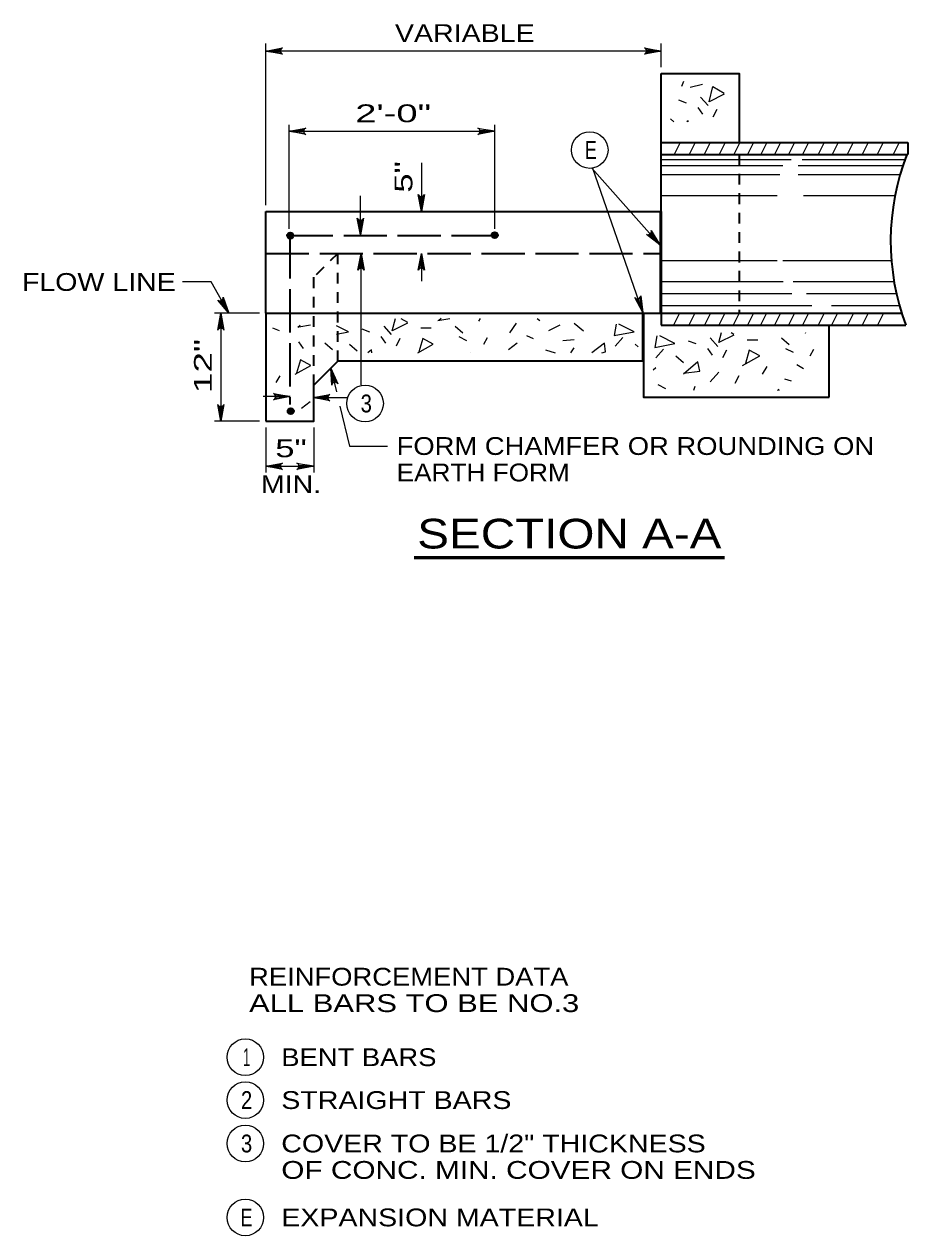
# Model space of a CAD drawing. Extents: x 2 to 114, y -129 to 32.
# Drawn here: x 65.3 to 114.4, y -35.3 to 32 of the extents above; entities that cross this region are included whole.
import ezdxf
from ezdxf.enums import TextEntityAlignment as Align

# ---------------------------------------------------------------- set-up
doc = ezdxf.new("R2010")
doc.units = 0
doc.header["$LTSCALE"] = 0.4
doc.linetypes.add('LONG_DASHED', pattern=[7.5, 6, -1.5])
doc.linetypes.add('SHORT_DASHED', pattern=[2.7, 1.5, -1.2])
for name, color, linetype, lineweight in [('1', 7, 'Continuous', 35), ('10', 7, 'Continuous', 13), ('12', 7, 'Continuous', 53), ('13', 7, 'Continuous', 25), ('6', 7, 'Continuous', 13)]:
    doc.layers.add(name, color=color, linetype=linetype, lineweight=lineweight)

msp = doc.modelspace()

# ---------------------------------------------------------------- linework, layer by layer
at = {"layer": '1'}
for p, q in [((100.7378, 21.6074), (100.7378, 29.2741)), ((100.7378, 25.4408), (114.4448, 25.4408)), ((114.4448, 25.4408), (114.4448, 24.7741)), ((100.7378, 24.7741), (114.4448, 24.7741)), ((78.7378, 21.6074), (100.7378, 21.6074)), ((78.7378, 15.9408), (78.7378, 21.6074)), ((100.7378, 21.6074), (100.7378, 15.2741)), ((78.7378, 15.9408), (100.7378, 15.9408)), ((78.7378, 15.9408), (78.7378, 9.9408)), ((100.7378, 15.9408), (114.1068, 15.9408)), ((100.7378, 15.2741), (114.3351, 15.2741)), ((110.0711, 11.2741), (110.0711, 15.2741))]:
    msp.add_line(p, q, dxfattribs=at)
at = {"layer": '1', "linetype": 'SHORT_DASHED'}
for p, q in [((105.0711, 24.7741), (105.0711, 15.9408)), ((82.7378, 19.2741), (81.4045, 17.9408)), ((82.7378, 13.2741), (82.7378, 19.2741)), ((81.4045, 11.9408), (81.4045, 17.9408))]:
    msp.add_line(p, q, dxfattribs=at)
at = {"layer": '1', "linetype": 'LONG_DASHED'}
for p, q in [((80.0711, 20.2741), (80.0711, 10.8778)), ((80.0711, 20.2741), (91.329, 20.2741)), ((78.7378, 19.2741), (100.7378, 19.2741))]:
    msp.add_line(p, q, dxfattribs=at)
at = {"layer": '1'}
for points in [[(100.7378, 29.2741), (105.0711, 29.2741), (105.0711, 25.4408)], [(99.7378, 15.9408), (99.7378, 11.2741), (110.0711, 11.2741)], [(99.7378, 13.2741), (82.7378, 13.2741), (81.4045, 11.9408)], [(78.7378, 9.9408), (81.4045, 9.9408), (81.4045, 11.9408)]]:
    msp.add_lwpolyline(points, dxfattribs=at)
for centre, radius in [((80.0977, 20.2589), 0.1667), ((80.0977, 20.2589), 0.125), ((80.0977, 20.2589), 0.0833), ((80.0977, 20.2589), 0.0417), ((91.4703, 20.2878), 0.1667), ((91.4703, 20.2878), 0.125), ((91.4703, 20.2878), 0.0833), ((91.4703, 20.2878), 0.0417), ((80.1266, 10.5014), 0.1667), ((80.1266, 10.5014), 0.125), ((80.1266, 10.5014), 0.0833), ((80.1266, 10.5014), 0.0417)]:
    msp.add_circle(centre, radius, dxfattribs=at)
msp.add_arc((126.916, 19.9558), 13.4238, 158.96483, 200.41147, dxfattribs=at)
at = {"layer": '10'}
for p, q in [((78.7378, 21.9574), (78.7378, 30.9362)), ((100.7378, 30.5196), (78.7378, 30.5196)), ((100.7378, 29.6241), (100.7378, 30.9362)), ((80.0398, 20.6378), (80.0398, 26.4135)), ((91.4703, 20.6378), (91.4703, 26.4135)), ((80.0398, 26.0635), (91.4703, 26.0635)), ((87.3901, 24.298), (87.3901, 21.6074)), ((96.8661, 24.0045), (100.6617, 19.7394)), ((96.9061, 24.0097), (99.4847, 16.5975)), ((84.0043, 20.3023), (84.0043, 22.4776)), ((84.035, 11.9581), (84.035, 19.2741)), ((87.3901, 19.2741), (87.3901, 17.7359)), ((78.3878, 15.9408), (75.8878, 15.9408)), ((76.2378, 15.9408), (76.2378, 9.9408)), ((82.3581, 12.8943), (82.6757, 11.5743)), ((80.0977, 11.3121), (78.5977, 11.3121)), ((81.371, 11.2542), (83.2519, 11.2542)), ((82.8651, 10.7872), (83.4001, 8.5636)), ((78.3878, 9.9408), (75.8878, 9.9408)), ((78.7378, 9.5908), (78.7378, 7.0908)), ((81.4045, 9.5908), (81.4045, 7.0908)), ((83.4001, 8.5636), (85.5161, 8.5636)), ((78.7378, 7.4408), (81.4045, 7.4408))]:
    msp.add_line(p, q, dxfattribs=at)
for points in [[(78.7378, 30.5196), (79.6699, 30.6943), (79.5981, 30.6446), (79.561, 30.5821), (79.5503, 30.5196), (79.561, 30.4571), (79.5981, 30.3946), (79.6699, 30.3448), (78.7378, 30.5196), (79.5981, 30.3946), (79.561, 30.4571), (78.7378, 30.5196), (79.5503, 30.5196), (79.561, 30.5821), (78.7378, 30.5196), (79.5981, 30.6446)], [(100.7378, 30.5196), (99.8057, 30.3448), (99.8776, 30.3946), (99.9146, 30.4571), (99.9253, 30.5196), (99.9146, 30.5821), (99.8776, 30.6446), (99.8057, 30.6943), (100.7378, 30.5196), (99.8776, 30.6446), (99.9146, 30.5821), (100.7378, 30.5196), (99.9253, 30.5196), (99.9146, 30.4571), (100.7378, 30.5196), (99.8776, 30.3946)], [(80.0398, 26.0635), (80.9719, 26.2383), (80.9001, 26.1885), (80.8631, 26.126), (80.8523, 26.0635), (80.8631, 26.001), (80.9001, 25.9385), (80.9719, 25.8887), (80.0398, 26.0635), (80.9001, 25.9385), (80.8631, 26.001), (80.0398, 26.0635), (80.8523, 26.0635), (80.8631, 26.126), (80.0398, 26.0635), (80.9001, 26.1885)], [(91.4703, 26.0635), (90.5383, 25.8887), (90.6101, 25.9385), (90.6471, 26.001), (90.6578, 26.0635), (90.6471, 26.126), (90.6101, 26.1885), (90.5383, 26.2383), (91.4703, 26.0635), (90.6101, 26.1885), (90.6471, 26.126), (91.4703, 26.0635), (90.6578, 26.0635), (90.6471, 26.001), (91.4703, 26.0635), (90.6101, 25.9385)], [(87.3901, 21.6074), (87.2153, 22.5395), (87.2651, 22.4677), (87.3276, 22.4306), (87.3901, 22.4199), (87.4526, 22.4306), (87.5151, 22.4677), (87.5648, 22.5395), (87.3901, 21.6074), (87.5151, 22.4677), (87.4526, 22.4306), (87.3901, 21.6074), (87.3901, 22.4199), (87.3276, 22.4306), (87.3901, 21.6074), (87.2651, 22.4677)], [(84.0043, 20.3023), (83.8296, 21.2344), (83.8793, 21.1626), (83.9418, 21.1255), (84.0043, 21.1148), (84.0668, 21.1255), (84.1293, 21.1626), (84.1791, 21.2344), (84.0043, 20.3023), (84.1293, 21.1626), (84.0668, 21.1255), (84.0043, 20.3023), (84.0043, 21.1148), (83.9418, 21.1255), (84.0043, 20.3023), (83.8793, 21.1626)], [(100.6617, 19.7394), (99.9115, 20.3195), (99.9964, 20.2989), (100.0677, 20.3128), (100.1215, 20.3463), (100.1611, 20.3959), (100.1832, 20.4651), (100.1726, 20.5518), (100.6617, 19.7394), (100.1832, 20.4651), (100.1611, 20.3959), (100.6617, 19.7394), (100.1215, 20.3463), (100.0677, 20.3128), (100.6617, 19.7394), (99.9964, 20.2989)], [(84.035, 19.2741), (84.2098, 18.342), (84.16, 18.4138), (84.0975, 18.4509), (84.035, 18.4616), (83.9725, 18.4509), (83.91, 18.4138), (83.8603, 18.342), (84.035, 19.2741), (83.91, 18.4138), (83.9725, 18.4509), (84.035, 19.2741), (84.035, 18.4616), (84.0975, 18.4509), (84.035, 19.2741), (84.16, 18.4138)], [(87.3901, 19.2741), (87.5648, 18.342), (87.5151, 18.4138), (87.4526, 18.4509), (87.3901, 18.4616), (87.3276, 18.4509), (87.2651, 18.4138), (87.2153, 18.342), (87.3901, 19.2741), (87.2651, 18.4138), (87.3276, 18.4509), (87.3901, 19.2741), (87.3901, 18.4616), (87.4526, 18.4509), (87.3901, 19.2741), (87.5151, 18.4138)], [(76.6821, 15.9408), (75.6991, 17.682), (74.1076, 17.682)], [(76.6821, 15.9408), (76.0717, 16.6665), (76.1503, 16.6284), (76.223, 16.6269), (76.2827, 16.6483), (76.3318, 16.6884), (76.368, 16.7513), (76.3761, 16.8383), (76.6821, 15.9408), (76.368, 16.7513), (76.3318, 16.6884), (76.6821, 15.9408), (76.2827, 16.6483), (76.223, 16.6269), (76.6821, 15.9408), (76.1503, 16.6284)], [(99.7049, 15.9776), (99.2559, 16.8128), (99.3251, 16.7595), (99.3959, 16.7431), (99.4587, 16.7518), (99.515, 16.781), (99.5633, 16.8352), (99.589, 16.9187), (99.7049, 15.9776), (99.5633, 16.8352), (99.515, 16.781), (99.7049, 15.9776), (99.4587, 16.7518), (99.3959, 16.7431), (99.7049, 15.9776), (99.3251, 16.7595)], [(76.2378, 15.9408), (76.4126, 15.0087), (76.3628, 15.0805), (76.3003, 15.1175), (76.2378, 15.1283), (76.1753, 15.1175), (76.1128, 15.0805), (76.0631, 15.0087), (76.2378, 15.9408), (76.1128, 15.0805), (76.1753, 15.1175), (76.2378, 15.9408), (76.2378, 15.1283), (76.3003, 15.1175), (76.2378, 15.9408), (76.3628, 15.0805)], [(82.3581, 12.8943), (82.746, 12.029), (82.6808, 12.0872), (82.6114, 12.1086), (82.5481, 12.1044), (82.4899, 12.0793), (82.4378, 12.0287), (82.4062, 11.9473), (82.3581, 12.8943), (82.4378, 12.0287), (82.4899, 12.0793), (82.3581, 12.8943), (82.5481, 12.1044), (82.6114, 12.1086), (82.3581, 12.8943), (82.6808, 12.0872)], [(80.0977, 11.3121), (79.1656, 11.1373), (79.2375, 11.1871), (79.2745, 11.2496), (79.2852, 11.3121), (79.2745, 11.3746), (79.2375, 11.4371), (79.1656, 11.4869), (80.0977, 11.3121), (79.2375, 11.4371), (79.2745, 11.3746), (80.0977, 11.3121), (79.2852, 11.3121), (79.2745, 11.2496), (80.0977, 11.3121), (79.2375, 11.1871)], [(76.2378, 9.9408), (76.0631, 10.8728), (76.1128, 10.801), (76.1753, 10.764), (76.2378, 10.7533), (76.3003, 10.764), (76.3628, 10.801), (76.4126, 10.8728), (76.2378, 9.9408), (76.3628, 10.801), (76.3003, 10.764), (76.2378, 9.9408), (76.2378, 10.7533), (76.1753, 10.764), (76.2378, 9.9408), (76.1128, 10.801)], [(81.371, 11.2542), (82.3031, 11.429), (82.2312, 11.3792), (82.1942, 11.3167), (82.1835, 11.2542), (82.1942, 11.1917), (82.2312, 11.1292), (82.3031, 11.0794), (81.371, 11.2542), (82.2312, 11.1292), (82.1942, 11.1917), (81.371, 11.2542), (82.1835, 11.2542), (82.1942, 11.3167), (81.371, 11.2542), (82.2312, 11.3792)], [(78.7378, 7.4408), (79.6699, 7.6155), (79.5981, 7.5658), (79.561, 7.5033), (79.5503, 7.4408), (79.561, 7.3783), (79.5981, 7.3158), (79.6699, 7.266), (78.7378, 7.4408), (79.5981, 7.3158), (79.561, 7.3783), (78.7378, 7.4408), (79.5503, 7.4408), (79.561, 7.5033), (78.7378, 7.4408), (79.5981, 7.5658)], [(81.4045, 7.4408), (80.4724, 7.266), (80.5442, 7.3158), (80.5813, 7.3783), (80.592, 7.4408), (80.5813, 7.5033), (80.5442, 7.5658), (80.4724, 7.6155), (81.4045, 7.4408), (80.5442, 7.5658), (80.5813, 7.5033), (81.4045, 7.4408), (80.592, 7.4408), (80.5813, 7.3783), (81.4045, 7.4408), (80.5442, 7.3158)]]:
    msp.add_lwpolyline(points, dxfattribs=at)
for centre in [(96.7535, 25.0174), (84.2586, 10.9296)]:
    msp.add_circle(centre, 1.0192, dxfattribs=at)
at = {"layer": '12'}
msp.add_line((86.9845, 2.3679), (104.2598, 2.3679), dxfattribs=at)
at = {"layer": '13'}
for centre in [(77.6014, -25.4092), (77.6014, -27.7921), (77.6014, -30.2049), (77.6014, -34.3154)]:
    msp.add_circle(centre, 1.0192, dxfattribs=at)
at = {"layer": '6'}
for p, q in [((101.9736, 28.8309), (101.859, 28.5444)), ((103.024, 28.6503), (102.3356, 28.4914)), ((101.7002, 27.8031), (102.1238, 27.6442)), ((102.9181, 27.9619), (103.3417, 27.4853)), ((102.7592, 27.3794), (103.024, 27.0088)), ((103.8182, 27.2735), (103.6064, 26.8499)), ((101.2499, 26.7475), (101.4354, 26.5852)), ((101.7778, 25.4408), (101.4444, 24.7741)), ((102.6201, 25.4408), (102.2867, 24.7741)), ((103.4497, 25.4408), (103.1164, 24.7741)), ((104.2795, 25.4408), (103.9461, 24.7741)), ((105.0966, 25.4408), (104.7632, 24.7741)), ((105.8634, 25.4408), (105.5301, 24.7741)), ((106.6051, 25.4408), (106.2718, 24.7741)), ((107.372, 25.4408), (107.0386, 24.7741)), ((108.1388, 25.4408), (107.8055, 24.7741)), ((108.9308, 25.4408), (108.5974, 24.7741)), ((109.7982, 25.4408), (109.4649, 24.7741)), ((110.5651, 25.4408), (110.2317, 24.7741)), ((111.4073, 25.4408), (111.074, 24.7741)), ((112.237, 25.4408), (111.9037, 24.7741)), ((113.0793, 25.4408), (112.7459, 24.7741)), ((113.9593, 25.4408), (113.6259, 24.7741)), ((100.7378, 24.4947), (107.9502, 24.4947)), ((108.5787, 24.4947), (114.2829, 24.4947)), ((100.7378, 24.1614), (107.4915, 24.1614)), ((100.7378, 23.6614), (107.3206, 23.6614)), ((108.3459, 24.1614), (114.1681, 24.1614)), ((108.3524, 23.6614), (114.0139, 23.6614)), ((100.7378, 22.4947), (107.1742, 22.4947)), ((108.6541, 22.4947), (113.7346, 22.4947)), ((100.6617, 21.6074), (100.6617, 15.9408)), ((100.7378, 18.8761), (107.1742, 18.8761)), ((107.4915, 18.8761), (113.5357, 18.8761)), ((100.7378, 17.7094), (107.5159, 17.7094)), ((108.0774, 17.7094), (113.6815, 17.7094)), ((100.7378, 17.0428), (108.0041, 17.0428)), ((108.8097, 17.0428), (113.8121, 17.0428)), ((100.7378, 16.3761), (109.1026, 16.3761)), ((110.2011, 16.3761), (113.9784, 16.3761)), ((86.2528, 15.6589), (86.6212, 15.444)), ((88.3157, 15.5499), (88.9697, 15.6589)), ((88.4958, 15.6589), (88.3686, 15.5499)), ((90.5926, 15.497), (90.6736, 15.6589)), ((93.8289, 15.6589), (93.9815, 15.5499)), ((99.6676, 15.9408), (99.6676, 13.2741)), ((101.7572, 15.9408), (101.4238, 15.2741)), ((102.5994, 15.9408), (102.2661, 15.2741)), ((103.4794, 15.9408), (103.1461, 15.2741)), ((104.2714, 15.9408), (103.938, 15.2741)), ((105.0634, 15.9408), (104.73, 15.2741)), ((105.8554, 15.9408), (105.522, 15.2741)), ((106.5845, 15.9408), (106.2511, 15.2741)), ((107.3639, 15.9408), (107.0306, 15.2741)), ((108.1433, 15.9408), (107.81, 15.2741)), ((108.9227, 15.9408), (108.5894, 15.2741)), ((109.8027, 15.9408), (109.4694, 15.2741)), ((110.5444, 15.9408), (110.2111, 15.2741)), ((111.4244, 15.9408), (111.0911, 15.2741)), ((112.2415, 15.9408), (111.9082, 15.2741)), ((113.0964, 15.9408), (112.763, 15.2741)), ((79.1075, 15.1396), (79.4782, 14.9808)), ((80.6554, 15.2617), (80.5282, 15.1527)), ((80.5745, 15.1924), (81.2285, 15.3014)), ((84.0796, 15.0734), (84.5032, 14.9145)), ((85.2974, 15.2322), (85.7211, 14.7557)), ((87.3625, 15.1263), (87.945, 15.1263)), ((89.2688, 15.2322), (89.6924, 14.8616)), ((92.6577, 15.3911), (92.287, 14.8616)), ((95.0934, 15.2852), (94.458, 14.9675)), ((95.8877, 15.3911), (96.4172, 14.9675)), ((104.6159, 14.882), (104.7794, 14.7866)), ((108.7508, 14.8396), (108.772, 14.882)), ((80.5534, 14.3519), (80.8182, 13.9812)), ((82.0216, 14.3056), (82.4452, 13.9349)), ((83.3912, 14.2261), (83.8148, 13.8555)), ((85.1386, 14.6498), (85.4034, 14.2791)), ((86.1976, 14.5438), (85.9858, 14.1202)), ((89.4806, 14.6498), (89.9042, 14.4379)), ((90.8573, 14.2261), (91.0691, 14.5968)), ((92.7106, 14.2791), (92.2341, 13.9084)), ((93.2401, 14.7027), (93.6108, 14.5438)), ((95.2523, 14.4379), (95.8877, 14.4909)), ((98.1646, 14.1202), (98.5882, 14.5968)), ((99.2766, 14.2261), (99.4524, 14.0723)), ((102.2378, 14.416), (102.6614, 14.2571)), ((103.4556, 14.5748), (103.8793, 14.0983)), ((105.5207, 14.4689), (106.1032, 14.4689)), ((107.427, 14.5748), (107.8506, 14.2042)), ((90.116, 13.7496), (90.1215, 13.7465)), ((94.2992, 13.9084), (94.8287, 13.7496)), ((95.7091, 13.7465), (95.8877, 14.0143)), ((100.4374, 13.4628), (100.861, 13.9394)), ((101.5494, 13.5687), (101.973, 13.1981)), ((103.2968, 13.9924), (103.5616, 13.6217)), ((104.3558, 13.8864), (104.144, 13.4628)), ((107.6388, 13.9924), (108.0624, 13.7806)), ((109.0155, 13.5687), (109.2274, 13.9394)), ((100.2886, 12.8058), (100.4374, 12.9333)), ((106.368, 12.5627), (106.6327, 12.9863)), ((108.2742, 13.0922), (108.6449, 12.8804)), ((79.325, 12.1011), (79.5368, 12.4718)), ((103.9322, 12.6686), (103.4556, 12.1391)), ((105.0442, 12.4568), (104.8324, 12.0332)), ((107.5859, 12.2979), (107.9565, 12.192)), ((100.5433, 11.9802), (100.9669, 11.7684)), ((102.6084, 11.8743), (102.5206, 11.6547)), ((81.1981, 11.022), (80.7216, 10.6514))]:
    msp.add_line(p, q, dxfattribs=at)
for points in [[(104.2418, 28.1208), (103.3946, 27.6972), (103.6064, 28.5444), (104.2418, 28.1737)], [(102.2402, 26.5858), (102.2297, 26.6381), (102.165, 26.582)], [(86.6212, 15.3911), (85.774, 14.9675), (85.9469, 15.6589)], [(82.668, 14.7868), (83.3382, 14.9145), (82.668, 15.2496)], [(98.2176, 15.3381), (98.1117, 14.7027), (99.2236, 14.9145), (98.3764, 15.3381)], [(104.7794, 14.7337), (103.9322, 14.3101), (104.0752, 14.882)], [(87.1875, 13.7465), (88.0509, 14.2261), (87.4684, 14.5438), (87.2566, 13.8025)], [(97.4221, 13.7465), (97.6351, 13.8025), (97.5822, 14.2791), (96.872, 13.7465)], [(100.4904, 14.6807), (100.3845, 14.0453), (101.4964, 14.2571), (100.6492, 14.6807)], [(84.6415, 13.7465), (84.6091, 13.9084), (84.4222, 13.7465)], [(105.256, 13.0392), (106.2091, 13.5687), (105.6266, 13.8864), (105.4148, 13.1451)], [(80.3792, 12.5549), (81.2426, 13.0345), (80.6602, 13.3522), (80.4484, 12.6109)], [(101.973, 12.6156), (102.8732, 12.7215), (102.7673, 13.251), (101.973, 12.5627)], [(107.2884, 11.6547), (107.2681, 11.7154), (107.1973, 11.6547)]]:
    msp.add_lwpolyline(points, dxfattribs=at)

# ---------------------------------------------------------------- texts
at = {"layer": '12', "width": 1.2}
for s, height, p in [('VARIABLE', 0.99, (89.8074, 31.0196)), ('MIN.', 0.99, (80.1407, 5.9508)), ('SECTION A-A', 1.65, (95.6221, 2.8679))]:
    msp.add_text(s, height=height, dxfattribs=at).set_placement(p, align=Align.CENTER)
at = {"layer": '12'}
for s, width, p in [('FLOW LINE', 1.2, (65.1729, 17.187)), ('FORM CHAMFER OR ROUNDING ON', 1.15, (86.0161, 8.0686)), ('EARTH FORM', 1.1, (86.0161, 6.5986))]:
    msp.add_text(s, height=0.99, dxfattribs=dict(at, width=width)).set_placement(p)
at = {"layer": '13'}
for s, width, p in [('2\'-0"', 1.6, (85.8247, 26.5635)), ('E', 0.75, (96.8231, 24.5224)), ('3', 0.85, (84.3282, 10.4346)), ('5"', 1.45, (80.1407, 7.9408)), ('1', 0.55, (77.6709, -25.9042)), ('2', 0.85, (77.6709, -28.2871)), ('3', 0.85, (77.6709, -30.6999)), ('E', 0.75, (77.671, -34.8104))]:
    msp.add_text(s, height=0.99, dxfattribs=dict(at, width=width)).set_placement(p, align=Align.CENTER)
for s, width, p in [('5"', 1.45, (86.8901, 23.5223)), ('12"', 1.55, (75.7378, 13.0103))]:
    msp.add_text(s, height=0.99, rotation=90, dxfattribs=dict(at, width=width)).set_placement(p, align=Align.CENTER)
for s, width, p in [('REINFORCEMENT DATA', 1.15, (77.8088, -21.4297)), ('ALL BARS TO BE NO.3', 1.3, (77.8088, -22.8998)), ('BENT BARS', 1.15, (79.6014, -25.9042)), ('STRAIGHT BARS', 1.2, (79.6014, -28.2871)), ('COVER TO BE 1/2" THICKNESS', 1.2, (79.6014, -30.6999)), ('OF CONC. MIN. COVER ON ENDS', 1.25, (79.6014, -32.1699)), ('EXPANSION MATERIAL', 1.2, (79.6014, -34.8104))]:
    msp.add_text(s, height=0.99, dxfattribs=dict(at, width=width)).set_placement(p)

doc.saveas('drawing.dxf')
